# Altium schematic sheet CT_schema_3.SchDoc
size 294 x 169 mm
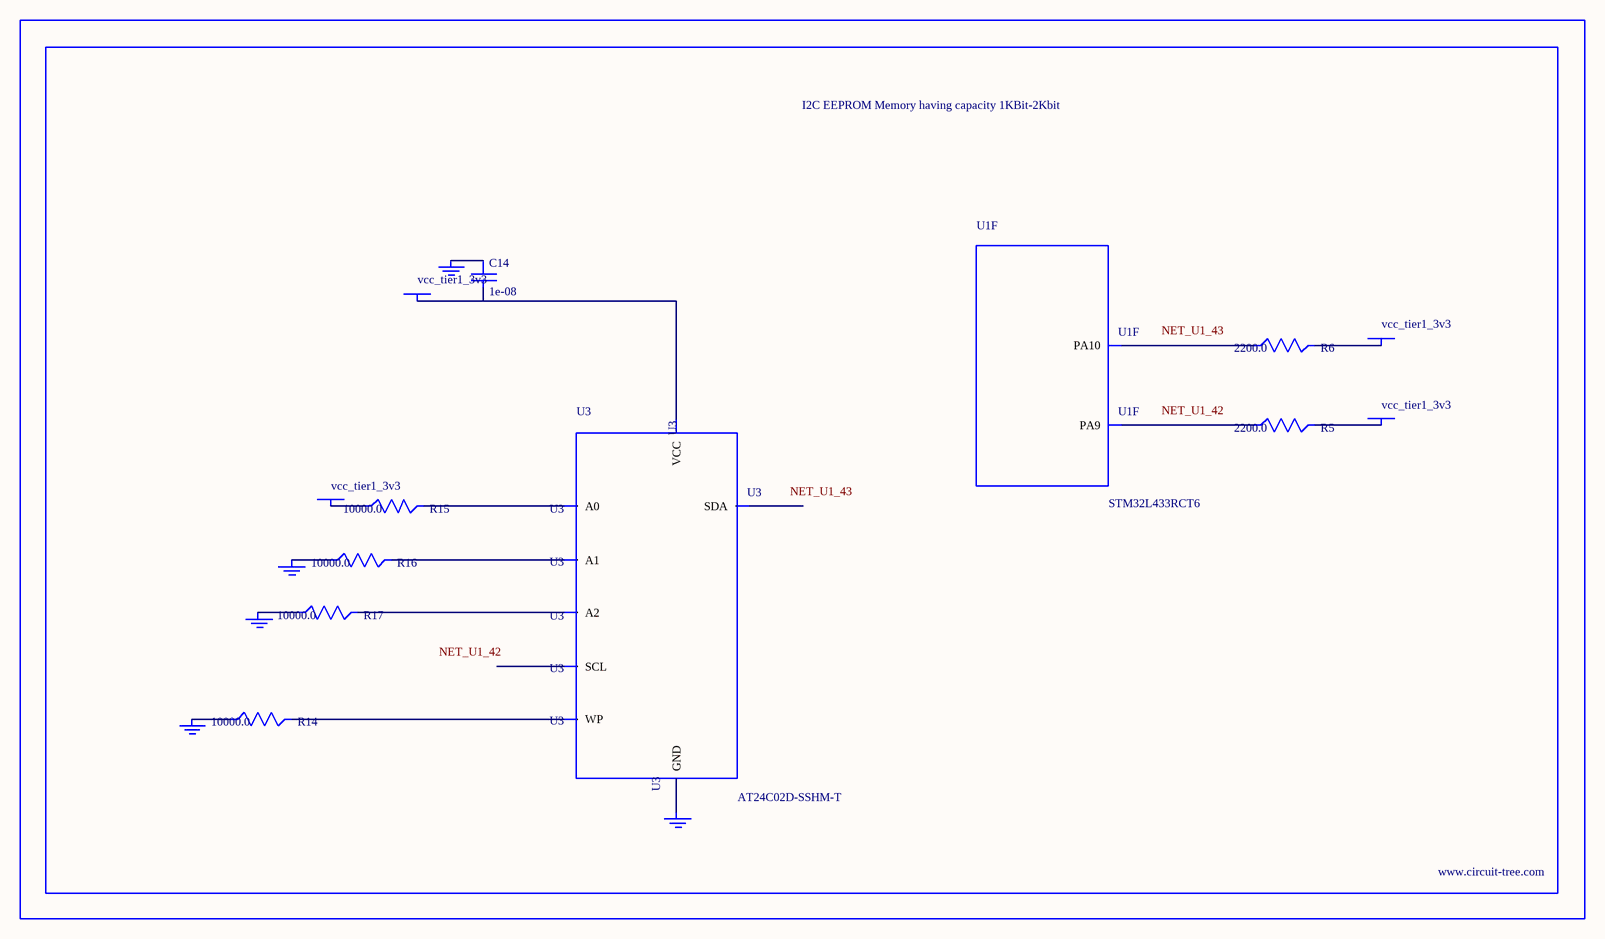
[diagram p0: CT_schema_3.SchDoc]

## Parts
BORDER2  (no value)
C14  1e-08  [C0402]
GND_INSTANCE_2_0  (no value)
GND_INSTANCE_2_1  (no value)
GND_INSTANCE_2_2  (no value)
GND_INSTANCE_2_3  (no value)
GND_INSTANCE_2_4  (no value)
POWER_INSTANCE_2_0  vcc_tier1_3v3
POWER_INSTANCE_2_1  vcc_tier1_3v3
POWER_INSTANCE_2_2  vcc_tier1_3v3
POWER_INSTANCE_2_3  vcc_tier1_3v3
R5  2200.0  [R0603]
R6  2200.0  [R0603]
R14  10000.0  [R0603]
R15  10000.0  [R0603]
R16  10000.0  [R0603]
R17  10000.0  [R0603]
U1  STM32L433RCT6  [LQFP64]  (part F of 8)
U3  AT24C02D-SSHM-T  [AT24C02D]

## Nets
NetC14_1: C14.1 GND_INSTANCE_2_3.0(GND)
NetC14_2: C14.2 POWER_INSTANCE_2_1.0(PWR) U3.8(VCC)
NetGND_INSTANCE_2_0_0: GND_INSTANCE_2_0.0(GND) R16.1
NetGND_INSTANCE_2_1_0: GND_INSTANCE_2_1.0(GND) R17.1
NetGND_INSTANCE_2_2_0: GND_INSTANCE_2_2.0(GND) R14.1
NetGND_INSTANCE_2_4_0: GND_INSTANCE_2_4.0(GND) U3.4(GND)
NetPOWER_INSTANCE_2_0_0: POWER_INSTANCE_2_0.0(PWR) R15.1
NetPOWER_INSTANCE_2_2_0: POWER_INSTANCE_2_2.0(PWR) R5.2
NetPOWER_INSTANCE_2_3_0: POWER_INSTANCE_2_3.0(PWR) R6.2
NetR5_1: R5.1 U1.42(PA9)
NetR6_1: R6.1 U1.43(PA10)
NetR14_2: R14.2 U3.7(WP)
NetR15_2: R15.2 U3.1(A0)
NetR16_2: R16.2 U3.2(A1)
NetR17_2: R17.2 U3.3(A2)

Not connected (* = marked no-connect by the designer): U3 5(SDA) 6(SCL)

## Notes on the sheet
- Labels drawn without touching a wire or pin: NET_U1_42, NET_U1_43

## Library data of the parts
BORDER2 = BORDER_PAGE2
C14 = C0402C103K3RAC
GND_INSTANCE_2_0-GND_INSTANCE_2_4 = GND
POWER_INSTANCE_2_0-POWER_INSTANCE_2_3 = PWR
R5 R6 = RC0603JR-072K2L
R14-R17 = RC0603JR-0710KL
